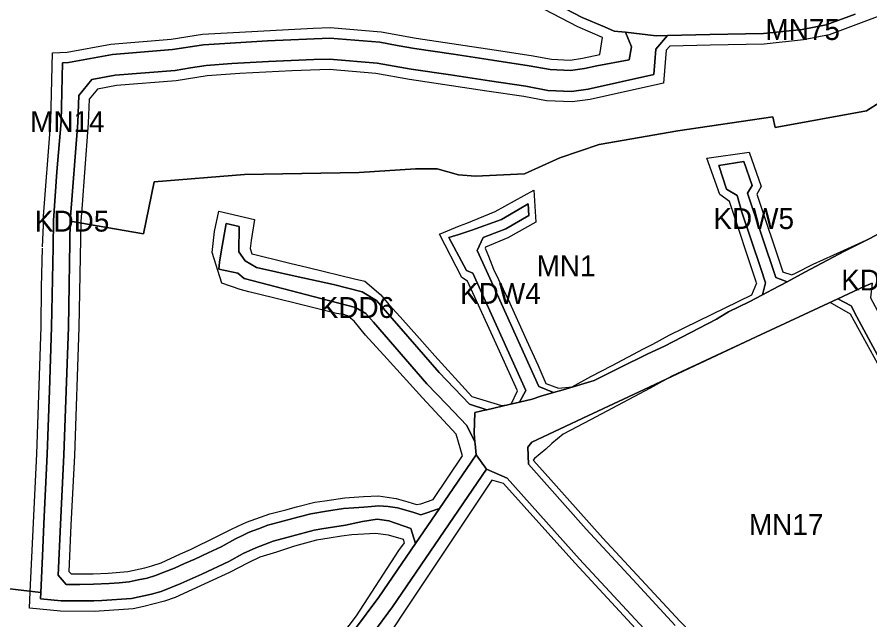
# Model space of a CAD drawing. Extents: x 7428841 to 7433518, y 5545054 to 5546840.
# Drawn here: x 7429914.7 to 7430323, y 5545549.4 to 5545838 of the extents above; entities that cross this region are included whole.
import ezdxf

# ---------------------------------------------------------------- set-up
doc = ezdxf.new("R2010")
doc.units = 0
for name, color, linetype in [('linie_rozgraniczajace', 7, 'Continuous'), ('linie_zabudowy_nieprzekraczalne', 7, 'Continuous'), ('oznaczenia_przeznaczen', 7, 'Continuous')]:
    doc.layers.add(name, color=color, linetype=linetype)

msp = doc.modelspace()

# ---------------------------------------------------------------- linework, layer by layer
at = {"layer": 'linie_rozgraniczajace'}
for points in [[(7430169.33, 5545846.21), (7430185.25, 5545837.88), (7430195.9, 5545833.29), (7430200.47, 5545831.32), (7430205.97, 5545830.79), (7430208.82, 5545823.76), (7430207.7, 5545817.55), (7430192.25, 5545814.69), (7430186.34, 5545813.37), (7430179.66, 5545812.42), (7430169.93, 5545812.84), (7430159.89, 5545814.72), (7430142.35, 5545817.43), (7430123.67, 5545820.21), (7430104.98, 5545822.99), (7430096.68, 5545824.46), (7430088.37, 5545825.93), (7430064.48, 5545827.95), (7430034.6, 5545826.7), (7430003.99, 5545824.8), (7429989.1, 5545822.41), (7429960.28, 5545820.09), (7429939.25, 5545816.26), (7429936.49, 5545816.11), (7429935.76, 5545787.95), (7429933.72, 5545763.86), (7429932.15, 5545740.67), (7429931.92, 5545727.83), (7429931.22, 5545689.64), (7429930.16, 5545659.23), (7429929.1, 5545628.76), (7429927.5, 5545595.43), (7429926.78, 5545579.96), (7429925.98, 5545562.57), (7429898.92, 5545565.83)], [(7430315.92, 5545839.47), (7430302.12, 5545834.26), (7430290.53, 5545832.05), (7430281.31, 5545831.07), (7430272.09, 5545830.1), (7430246.37, 5545829.6), (7430226.1, 5545829.18), (7430220.66, 5545829.1), (7430205.97, 5545830.79), (7430200.47, 5545831.32), (7430195.9, 5545833.29), (7430185.25, 5545837.88), (7430169.33, 5545846.21)], [(7430340.97, 5545805.64), (7430321.42, 5545793.16), (7430277.64, 5545785.19), (7430276.43, 5545790.2), (7430230.98, 5545783.53), (7430193.3, 5545777.02), (7430174.47, 5545770.6), (7430157.62, 5545762.9), (7430134.22, 5545761.86), (7430126, 5545762.51), (7430115.77, 5545765.43), (7430105.43, 5545765.42), (7430078.43, 5545763.66), (7430023.54, 5545762.58), (7429980.32, 5545759.16), (7429975.14, 5545734.21), (7429940.14, 5545740.33), (7429943.75, 5545787.47), (7429944.2, 5545800.54), (7429950.49, 5545808.15), (7429961.57, 5545810.17), (7429975.93, 5545811.32), (7429990.29, 5545812.47), (7429997.72, 5545813.67), (7430005.14, 5545814.86), (7430017.46, 5545815.73), (7430035.11, 5545816.71), (7430056.74, 5545817.69), (7430064.22, 5545817.93), (7430087.08, 5545816), (7430103.38, 5545813.12), (7430122.11, 5545810.33), (7430140.85, 5545807.55), (7430158.2, 5545804.86), (7430168.79, 5545802.88), (7430180.15, 5545802.39), (7430188.14, 5545803.52), (7430219.48, 5545810.53), (7430220.52, 5545822.61), (7430226.1, 5545829.18), (7430246.37, 5545829.6), (7430272.09, 5545830.1), (7430281.31, 5545831.07), (7430290.53, 5545832.05), (7430302.12, 5545834.26), (7430315.92, 5545839.47)], [(7429925.82, 5545559.59), (7429925.98, 5545562.57), (7429926.78, 5545579.96), (7429927.5, 5545595.43), (7429929.1, 5545628.76), (7429930.16, 5545659.23), (7429931.22, 5545689.64), (7429931.92, 5545727.83), (7429932.15, 5545740.67), (7429933.72, 5545763.86), (7429935.76, 5545787.95), (7429936.49, 5545816.11), (7429939.25, 5545816.26), (7429960.28, 5545820.09), (7429989.1, 5545822.41), (7430003.99, 5545824.8), (7430034.6, 5545826.7), (7430064.48, 5545827.95), (7430088.37, 5545825.93), (7430096.68, 5545824.46), (7430104.98, 5545822.99), (7430123.67, 5545820.21), (7430142.35, 5545817.43), (7430159.89, 5545814.72), (7430169.93, 5545812.84), (7430179.66, 5545812.42), (7430186.34, 5545813.37), (7430192.25, 5545814.69), (7430207.7, 5545817.55), (7430208.82, 5545823.76), (7430205.97, 5545830.79), (7430220.66, 5545829.1), (7430226.1, 5545829.18), (7430220.52, 5545822.61), (7430219.48, 5545810.53), (7430188.14, 5545803.52), (7430180.15, 5545802.39), (7430168.79, 5545802.88), (7430158.2, 5545804.86), (7430140.85, 5545807.55), (7430122.11, 5545810.33), (7430103.38, 5545813.12), (7430087.08, 5545816), (7430064.22, 5545817.93), (7430056.74, 5545817.69), (7430035.11, 5545816.71), (7430017.46, 5545815.73), (7430005.14, 5545814.86), (7429997.72, 5545813.67), (7429990.29, 5545812.47), (7429975.93, 5545811.32), (7429961.57, 5545810.17), (7429950.49, 5545808.15), (7429944.2, 5545800.54), (7429943.75, 5545787.47), (7429940.14, 5545740.33), (7429939.22, 5545689.5), (7429937.1, 5545628.42), (7429935.49, 5545595.05), (7429934.32, 5545570.91), (7429938.24, 5545566.4), (7429944.73, 5545566.45), (7429951.23, 5545566.51), (7429958.68, 5545566.89), (7429963.52, 5545567.27), (7429968.36, 5545567.65), (7429972.69, 5545568.55), (7429977.02, 5545569.46), (7429981.01, 5545570.67), (7429985.48, 5545572.46), (7429989.96, 5545574.26), (7429994.86, 5545576.42), (7429999.76, 5545578.57), (7430006.09, 5545581.53), (7430012.42, 5545584.49), (7430019.3, 5545588.29), (7430022.54, 5545589.83), (7430025.79, 5545591.38), (7430030.28, 5545593.05), (7430034.78, 5545594.73), (7430039.45, 5545596), (7430049.69, 5545598.76), (7430055.26, 5545600.25), (7430062.8, 5545601.51), (7430071.01, 5545602.78), (7430075.88, 5545603.12), (7430080.75, 5545603.46), (7430084.31, 5545603.71), (7430087.88, 5545603.97), (7430090.11, 5545603.89), (7430092.34, 5545603.8), (7430094.61, 5545603.47), (7430096.87, 5545603.14), (7430100.74, 5545602.03), (7430104.61, 5545600.91), (7430107.95, 5545599.71), (7430116.88, 5545602.74), (7430105.45, 5545586.04), (7430103.17, 5545593.17), (7430092.73, 5545596.91)], [(7429934.32, 5545570.91), (7429935.49, 5545595.05), (7429937.1, 5545628.42), (7429939.22, 5545689.5), (7429940.14, 5545740.33), (7429975.14, 5545734.21), (7429980.32, 5545759.16), (7430023.54, 5545762.58), (7430078.43, 5545763.66), (7430105.43, 5545765.42), (7430115.77, 5545765.43), (7430126, 5545762.51), (7430134.22, 5545761.86), (7430157.62, 5545762.9), (7430174.47, 5545770.6), (7430193.3, 5545777.02), (7430230.98, 5545783.53), (7430276.43, 5545790.2), (7430277.64, 5545785.19), (7430321.42, 5545793.16), (7430340.97, 5545805.64)], [(7430338.17, 5545740.16), (7430322.99, 5545732.04), (7430311.07, 5545726.05), (7430310.84, 5545725.92), (7430291.89, 5545715.89), (7430283.36, 5545711.3), (7430277.88, 5545713.38), (7430264.39, 5545753.66), (7430266.54, 5545757.37), (7430262.57, 5545768.89), (7430250.66, 5545767.02), (7430254.37, 5545755.65), (7430259.48, 5545752.59), (7430261.71, 5545744.58), (7430270.77, 5545717.61), (7430273.07, 5545710.78), (7430271.54, 5545705.08), (7430265.13, 5545701.78), (7430255.26, 5545696.94), (7430253.62, 5545695.93), (7430249.55, 5545693.42), (7430224.68, 5545680.42), (7430216.7, 5545676.85), (7430202.78, 5545669.94), (7430191.04, 5545664.12), (7430176.13, 5545659.6), (7430171.46, 5545658.27), (7430164.4, 5545661.17), (7430144.32, 5545705.72), (7430139.44, 5545716.46), (7430134.98, 5545726.35), (7430137.75, 5545732.56), (7430148.64, 5545736.62), (7430159.73, 5545743.05), (7430159.3, 5545748.66), (7430155.05, 5545746.11), (7430146.52, 5545741.16), (7430132.45, 5545735.93), (7430126.19, 5545733.86), (7430121.39, 5545732.46), (7430129.78, 5545716.72), (7430132.84, 5545715.44), (7430158.21, 5545659.29), (7430155.2, 5545653.68), (7430150.21, 5545652.52), (7430139.63, 5545650.06), (7430131.23, 5545652.76), (7430116.75, 5545667.9), (7430101.78, 5545685.13), (7430086.82, 5545702.36), (7430079.81, 5545706.46)], [(7430079.81, 5545706.46), (7430066.18, 5545709.92), (7430047.75, 5545714.02), (7430029.32, 5545718.12), (7430023.93, 5545721.26), (7430020.77, 5545725.57), (7430020.98, 5545737.69), (7430014.83, 5545739.15), (7430012.45, 5545725.61), (7430011.58, 5545720.68), (7430011.29, 5545717.4), (7430020.31, 5545715.45), (7430023.37, 5545712.92), (7430064.33, 5545702.13), (7430076.75, 5545698.98), (7430081.64, 5545696.12), (7430085.35, 5545691.99), (7430110.84, 5545662.51), (7430120.39, 5545652.51), (7430129.95, 5545642.51), (7430133.85, 5545634.69), (7430133.95, 5545633.65), (7430134.46, 5545628.43), (7430116.88, 5545602.74), (7430107.95, 5545599.71), (7430104.61, 5545600.91), (7430100.74, 5545602.03), (7430096.87, 5545603.14), (7430094.61, 5545603.47), (7430092.34, 5545603.8), (7430090.11, 5545603.89), (7430087.88, 5545603.97), (7430084.31, 5545603.71), (7430080.75, 5545603.46), (7430075.88, 5545603.12), (7430071.01, 5545602.78), (7430062.8, 5545601.51), (7430055.26, 5545600.25), (7430049.69, 5545598.76), (7430039.45, 5545596), (7430034.78, 5545594.73), (7430030.28, 5545593.05), (7430025.79, 5545591.38), (7430022.54, 5545589.83), (7430019.3, 5545588.29), (7430012.42, 5545584.49), (7430006.09, 5545581.53), (7429999.76, 5545578.57), (7429994.86, 5545576.42), (7429989.96, 5545574.26), (7429985.48, 5545572.46), (7429981.01, 5545570.67), (7429977.02, 5545569.46), (7429972.69, 5545568.55), (7429968.36, 5545567.65), (7429963.52, 5545567.27), (7429958.68, 5545566.89), (7429951.23, 5545566.51), (7429944.73, 5545566.45), (7429938.24, 5545566.4), (7429934.32, 5545570.91)], [(7430133.44, 5545638.87), (7430133.83, 5545648.7), (7430139.22, 5545649.96), (7430139.63, 5545650.06), (7430150.21, 5545652.52), (7430155.2, 5545653.68), (7430161.21, 5545655.08), (7430165.39, 5545656.53), (7430171.46, 5545658.27), (7430176.13, 5545659.6), (7430191.04, 5545664.12), (7430202.78, 5545669.94), (7430216.7, 5545676.85), (7430224.68, 5545680.42), (7430249.55, 5545693.42), (7430253.62, 5545695.93), (7430255.26, 5545696.94), (7430265.13, 5545701.78), (7430271.54, 5545705.08), (7430276.34, 5545707.62), (7430283.36, 5545711.3), (7430291.89, 5545715.89), (7430310.84, 5545725.92), (7430311.07, 5545726.05), (7430322.99, 5545732.04), (7430338.17, 5545740.16)], [(7430324.14, 5545710.6), (7430320.24, 5545709.08), (7430307.55, 5545703.17), (7430268.56, 5545685.01), (7430214.85, 5545659.79), (7430188, 5545647.19), (7430161.15, 5545634.58), (7430159.13, 5545632.06), (7430159.46, 5545623.96), (7430187.12, 5545592.88), (7430211.33, 5545566.73), (7430229.77, 5545546.84)], [(7430356.4, 5545538.02), (7430359.72, 5545551.27), (7430364.23, 5545562.59), (7430368.74, 5545573.91), (7430370.39, 5545580.44), (7430370.65, 5545587.94), (7430369.28, 5545596.66), (7430345.47, 5545641.25), (7430316.75, 5545694.49), (7430313.95, 5545699.78), (7430307.55, 5545703.17), (7430320.24, 5545709.08), (7430324.14, 5545710.6), (7430323.19, 5545703.65), (7430349.47, 5545654.88), (7430358.51, 5545638.06), (7430369.81, 5545617.05), (7430374.39, 5545608.67), (7430378.99, 5545599.31), (7430380.68, 5545588.55), (7430380.35, 5545579.03), (7430379.33, 5545575.09), (7430378.27, 5545570.82), (7430369.25, 5545548.19)], [(7430229.77, 5545546.84), (7430211.33, 5545566.73), (7430187.12, 5545592.88), (7430159.46, 5545623.96), (7430159.13, 5545632.06), (7430161.15, 5545634.58), (7430188, 5545647.19), (7430214.85, 5545659.79), (7430268.56, 5545685.01), (7430307.55, 5545703.17), (7430313.95, 5545699.78), (7430316.75, 5545694.49), (7430345.47, 5545641.25), (7430369.28, 5545596.66), (7430370.65, 5545587.94), (7430370.39, 5545580.44), (7430368.74, 5545573.91), (7430364.23, 5545562.59), (7430359.72, 5545551.27), (7430356.4, 5545538.02)], [(7430325.58, 5545455.53), (7430312.26, 5545461.16), (7430308.65, 5545461.94), (7430303.75, 5545463), (7430294.58, 5545464.99), (7430289.44, 5545468.09), (7430288.37, 5545469.23), (7430255.3, 5545503.38), (7430229.22, 5545530.19), (7430216.84, 5545543.13), (7430184.02, 5545578.55), (7430149.29, 5545617.28), (7430139.47, 5545621.59), (7430134.46, 5545628.43), (7430133.95, 5545633.65), (7430133.85, 5545634.69), (7430133.44, 5545638.87)], [(7430069.26, 5545535.23), (7430087.86, 5545560.33), (7430105.45, 5545586.04), (7430116.88, 5545602.74), (7430134.46, 5545628.43), (7430139.47, 5545621.59), (7430094.37, 5545555.69), (7430075.51, 5545530.23)], [(7430075.51, 5545530.23), (7430094.37, 5545555.69), (7430139.47, 5545621.59), (7430149.29, 5545617.28), (7430184.02, 5545578.55), (7430216.84, 5545543.13)], [(7429898.92, 5545565.83), (7429925.98, 5545562.57), (7429925.82, 5545559.59), (7429935.77, 5545558.61), (7429951.41, 5545558.5), (7429955.3, 5545558.7), (7429969.5, 5545559.72), (7429978.99, 5545561.7), (7429983.65, 5545563.11), (7429993.06, 5545566.88), (7430003.07, 5545571.29), (7430016.05, 5545577.36), (7430022.95, 5545581.17), (7430028.91, 5545584.01), (7430033.07, 5545585.55), (7430037.22, 5545587.1), (7430046.21, 5545589.54), (7430056.96, 5545592.43), (7430060.51, 5545593.02), (7430071.9, 5545594.83), (7430080.11, 5545596.61), (7430087.06, 5545597.64), (7430092.73, 5545596.91), (7430103.17, 5545593.17), (7430105.45, 5545586.04), (7430087.86, 5545560.33), (7430069.26, 5545535.23)], [(7430092.73, 5545596.91), (7430087.06, 5545597.64), (7430080.11, 5545596.61), (7430071.9, 5545594.83), (7430060.51, 5545593.02), (7430056.96, 5545592.43), (7430046.21, 5545589.54), (7430037.22, 5545587.1), (7430033.07, 5545585.55), (7430028.91, 5545584.01), (7430022.95, 5545581.17), (7430016.05, 5545577.36), (7430003.07, 5545571.29), (7429993.06, 5545566.88), (7429983.65, 5545563.11), (7429978.99, 5545561.7), (7429969.5, 5545559.72), (7429955.3, 5545558.7), (7429951.41, 5545558.5), (7429935.77, 5545558.61), (7429925.82, 5545559.59)]]:
    msp.add_lwpolyline(points, dxfattribs=at)
for points in [[(7430250.66, 5545767.02), (7430262.57, 5545768.89), (7430266.54, 5545757.37), (7430264.39, 5545753.66), (7430277.88, 5545713.38), (7430283.36, 5545711.3), (7430276.34, 5545707.62), (7430271.54, 5545705.08), (7430273.07, 5545710.78), (7430270.77, 5545717.61), (7430261.71, 5545744.58), (7430259.48, 5545752.59), (7430254.37, 5545755.65)], [(7430121.39, 5545732.46), (7430126.19, 5545733.86), (7430132.45, 5545735.93), (7430146.52, 5545741.16), (7430155.05, 5545746.11), (7430159.3, 5545748.66), (7430159.73, 5545743.05), (7430148.64, 5545736.62), (7430137.75, 5545732.56), (7430134.98, 5545726.35), (7430139.44, 5545716.46), (7430144.32, 5545705.72), (7430164.4, 5545661.17), (7430171.46, 5545658.27), (7430165.39, 5545656.53), (7430161.21, 5545655.08), (7430155.2, 5545653.68), (7430158.21, 5545659.29), (7430132.84, 5545715.44), (7430129.78, 5545716.72)], [(7430011.29, 5545717.4), (7430011.58, 5545720.68), (7430012.45, 5545725.61), (7430014.83, 5545739.15), (7430020.98, 5545737.69), (7430020.77, 5545725.57), (7430023.93, 5545721.26), (7430029.32, 5545718.12), (7430047.75, 5545714.02), (7430066.18, 5545709.92), (7430079.81, 5545706.46), (7430086.82, 5545702.36), (7430101.78, 5545685.13), (7430116.75, 5545667.9), (7430131.23, 5545652.76), (7430139.63, 5545650.06), (7430139.22, 5545649.96), (7430133.83, 5545648.7), (7430133.44, 5545638.87), (7430133.85, 5545634.69), (7430129.95, 5545642.51), (7430120.39, 5545652.51), (7430110.84, 5545662.51), (7430085.35, 5545691.99), (7430081.64, 5545696.12), (7430076.75, 5545698.98), (7430064.33, 5545702.13), (7430023.37, 5545712.92), (7430020.31, 5545715.45)]]:
    msp.add_lwpolyline(points, close=True, dxfattribs=at)
at = {"layer": 'linie_zabudowy_nieprzekraczalne'}
for points in [[(7430366.4, 5546116.12), (7430363.84, 5546113.37), (7430374.13, 5546089.96), (7430378.09, 5546081.11), (7430382.22, 5546072.73), (7430386.73, 5546063.75), (7430391.27, 5546052.21), (7430395.69, 5546042.42), (7430441.19, 5545984.49), (7430446.85, 5545972.27), (7430450.2, 5545954.23), (7430434.51, 5545925.37), (7430428.82, 5545918.32), (7430411.23, 5545900.22), (7430383.04, 5545871.75), (7430360.88, 5545854.96), (7430351.13, 5545848.75), (7430331.61, 5545840.06), (7430303.48, 5545829.43), (7430291.26, 5545827.1), (7430272.4, 5545825.1), (7430246.47, 5545824.6), (7430227.18, 5545824.13)], [(7430194.95, 5545828.25), (7430183.1, 5545833.36), (7430150.94, 5545850.19), (7430140.26, 5545856.78), (7430133.39, 5545860.05), (7430109.89, 5545873.08), (7430094.72, 5545880.3), (7430063.87, 5545895.09), (7430044.53, 5545899.82), (7430020.84, 5545901), (7430000.68, 5545897.77), (7429978.58, 5545891.84), (7429942.92, 5545884.02), (7429926.67, 5545880.46), (7429922.24, 5545879.01), (7429907.5, 5545873.33)], [(7429926.92, 5545727.98), (7429927.33, 5545738.36), (7429927.13, 5545740.65), (7429930.76, 5545788.2), (7429931.61, 5545820.85), (7429938.66, 5545821.23), (7429959.63, 5545825.06), (7429988.5, 5545827.37), (7430003.46, 5545829.78), (7430056.44, 5545832.69), (7430064.61, 5545832.95), (7430089.02, 5545830.89), (7430105.79, 5545827.92), (7430143.1, 5545822.38), (7430160.73, 5545819.65), (7430170.5, 5545817.82), (7430179.41, 5545817.43), (7430185.44, 5545818.29), (7430193.73, 5545820.14), (7430194.95, 5545828.25)], [(7430227.18, 5545824.13), (7430225.5, 5545822.18), (7430224.14, 5545806.45), (7430189.04, 5545798.6), (7430180.39, 5545797.38), (7430168.22, 5545797.9), (7430157.36, 5545799.93), (7430139.61, 5545802.6), (7430102.57, 5545808.18), (7430086.43, 5545811.04), (7430064.09, 5545812.93), (7430046.15, 5545812.21), (7430021.28, 5545810.96), (7430005.72, 5545809.89), (7429990.89, 5545807.5), (7429962.22, 5545805.2), (7429953.18, 5545803.56), (7429949.14, 5545798.66), (7429948.74, 5545787.19), (7429946.94, 5545763.64), (7429945.89, 5545748.31), (7429945.14, 5545740.09), (7429944.22, 5545689.37), (7429942.09, 5545628.22), (7429940.48, 5545594.81), (7429939.41, 5545572.67), (7429940.5, 5545571.42), (7429951.08, 5545571.5), (7429958.36, 5545571.88), (7429967.75, 5545572.62), (7429975.78, 5545574.3), (7429979.17, 5545575.36), (7429983.68, 5545576.82), (7429992.86, 5545581), (7429997.69, 5545583.13), (7430010.29, 5545589.44), (7430017.01, 5545592.74), (7430020.43, 5545594.36), (7430024.5, 5545596.25), (7430035.7, 5545600.16), (7430043.27, 5545602.2), (7430048.39, 5545603.59), (7430057.19, 5545605.74), (7430062, 5545606.44), (7430071.63, 5545607.87), (7430080.49, 5545608.45), (7430087.68, 5545608.78), (7430091.88, 5545608.18), (7430096.09, 5545607.59), (7430101.78, 5545605.89), (7430105.83, 5545604.72), (7430108, 5545605.01), (7430113.85, 5545607.03)], [(7430268.76, 5545710.78), (7430255.78, 5545749.79), (7430251.08, 5545753.1), (7430244.89, 5545770.55), (7430265.22, 5545773.36), (7430270.91, 5545756.93), (7430268.9, 5545753.25), (7430281.22, 5545716.01)], [(7430116.84, 5545734.02), (7430126.56, 5545738.03), (7430130.01, 5545739.37), (7430143.62, 5545744.92), (7430162.11, 5545755.09), (7430162.96, 5545739.76), (7430149.71, 5545732.28), (7430138.95, 5545727.93), (7430138.71, 5545727.34)], [(7430124.95, 5545638.35), (7430124.95, 5545638.35), (7430108.85, 5545655.68), (7430091.84, 5545674.44), (7430081.51, 5545685.73), (7430076, 5545692.41), (7430074.4, 5545693.73), (7430072.8, 5545695.05), (7430071.05, 5545695.56), (7430067.64, 5545696.15), (7430050.29, 5545700.4), (7430037.5, 5545703.6), (7430025.7, 5545706.46), (7430021.41, 5545707.58), (7430012.74, 5545710.56), (7430008.02, 5545725.32), (7430009.23, 5545735.32), (7430011.29, 5545745.11)], [(7430011.29, 5545745.11), (7430028.29, 5545741.12)], [(7430028.29, 5545741.12), (7430026.67, 5545731.07), (7430026.3, 5545727.26), (7430027.11, 5545724.72), (7430029.07, 5545724.23), (7430031.64, 5545723.61), (7430039.45, 5545721.69), (7430045.32, 5545720.23), (7430054.1, 5545718.14), (7430076.26, 5545712.76), (7430081.1, 5545711.56), (7430088.85, 5545705.13), (7430092.68, 5545700.41), (7430098.16, 5545694.46), (7430107.41, 5545684.12), (7430114.71, 5545675.79), (7430132.43, 5545656.43), (7430146.61, 5545652.05)], [(7430285.54, 5545714.56), (7430287.4, 5545715.48), (7430295.74, 5545719.71), (7430310.61, 5545726.39), (7430322.99, 5545732.04), (7430338.17, 5545740.16)], [(7430130.4, 5545711.54), (7430127.65, 5545713.27), (7430116.84, 5545734.02)], [(7429920.98, 5545562.81), (7429924.11, 5545628.96), (7429926.22, 5545689.75), (7429926.31, 5545708.71), (7429926.92, 5545727.42)], [(7430138.71, 5545727.34), (7430140.45, 5545723.53), (7430142.77, 5545717.3), (7430149.86, 5545702.85), (7430158.62, 5545683.33), (7430163.95, 5545671.49), (7430167.86, 5545662.58), (7430173.85, 5545660.36)], [(7430281.11, 5545716.04), (7430285.54, 5545714.56)], [(7430151.21, 5545652.77), (7430154.25, 5545659.07), (7430142.44, 5545685.07), (7430130.4, 5545711.54)], [(7430266.48, 5545705.07), (7430268.78, 5545710.81)], [(7430173.85, 5545660.36), (7430180.39, 5545660.99), (7430189.34, 5545665.94), (7430199.59, 5545671.23), (7430214.61, 5545679.16), (7430219.09, 5545681.49), (7430226.89, 5545685.69), (7430240.94, 5545692.68), (7430266.48, 5545705.07)], [(7430303.88, 5545701.34), (7430300.86, 5545699.93), (7430289.09, 5545694.58), (7430270.64, 5545685.98), (7430228.21, 5545666.1), (7430217.71, 5545660.42), (7430202.11, 5545652.12), (7430189.22, 5545645.28), (7430176.07, 5545638.39), (7430170.7, 5545633.94), (7430167.85, 5545631.23)], [(7430352.62, 5545523.31), (7430351.71, 5545527.21), (7430351.75, 5545535.04), (7430352.52, 5545541), (7430355.29, 5545549.4), (7430364.94, 5545573.76), (7430365.95, 5545577.43), (7430366.53, 5545582.28), (7430366.66, 5545589.17), (7430365.98, 5545593.7), (7430362.88, 5545602.83), (7430357.63, 5545614.99), (7430346.86, 5545634.84), (7430334.97, 5545656.8), (7430326.8, 5545671.95), (7430319.76, 5545684.81), (7430313.72, 5545695.75), (7430303.88, 5545701.34)], [(7430160.38, 5545667.71), (7430160.38, 5545667.71)], [(7430163.05, 5545668.82), (7430163.05, 5545668.82)], [(7430146.61, 5545652.05), (7430150.21, 5545652.52)], [(7430113.85, 5545607.03), (7430127.91, 5545628.05), (7430124.95, 5545638.35)], [(7430167.85, 5545631.23), (7430162.47, 5545626.69), (7430161.79, 5545625.86), (7430166.3, 5545621), (7430195.12, 5545588.64), (7430231.95, 5545548.9), (7430299.06, 5545479.91), (7430300.36, 5545479.08), (7430309.83, 5545477.03)], [(7430141.98, 5545616.32), (7430099.17, 5545552.22), (7430091.9, 5545541.01)], [(7430212.69, 5545543.2), (7430181.8, 5545576.54), (7430167.38, 5545592.73), (7430147.49, 5545614.79), (7430141.98, 5545616.32)], [(7430100.17, 5545586.26), (7430099.73, 5545587.92), (7430092.43, 5545589.93), (7430086.22, 5545590.81), (7430075.02, 5545590.18), (7430070.03, 5545589.53), (7430064.11, 5545588.55), (7430058.02, 5545587.54), (7430047.51, 5545584.71), (7430038.95, 5545581.95), (7430030.86, 5545579.4), (7430025.24, 5545576.72), (7430016.37, 5545572.08), (7429990.36, 5545560.2), (7429985.31, 5545558.39), (7429975.35, 5545555.85), (7429970.28, 5545554.75), (7429958.73, 5545553.88), (7429951.52, 5545553.5), (7429935.51, 5545553.61), (7429920.58, 5545555.09), (7429920.98, 5545562.81)], [(7430067.07, 5545538.1), (7430077.15, 5545551.35), (7430097.48, 5545582.68), (7430100.17, 5545586.26)]]:
    msp.add_lwpolyline(points, dxfattribs=at)

# ---------------------------------------------------------------- texts
at = {"layer": 'oznaczenia_przeznaczen'}
for s, p in [('MN75', (7430272.97, 5545827.05)), ('MN14', (7429920.92, 5545782.95)), ('KDD5', (7429923.18, 5545735.33)), ('KDW5', (7430248.03, 5545736.55)), ('MN1', (7430163.39, 5545713.94)), ('KDD12', (7430309.26, 5545707.13)), ('KDW4', (7430126.76, 5545700.72)), ('KDD6', (7430059.54, 5545693.98)), ('MN17', (7430265.05, 5545590.09))]:
    msp.add_text(s, height=10, dxfattribs=at).set_placement(p)

doc.saveas('drawing.dxf')
